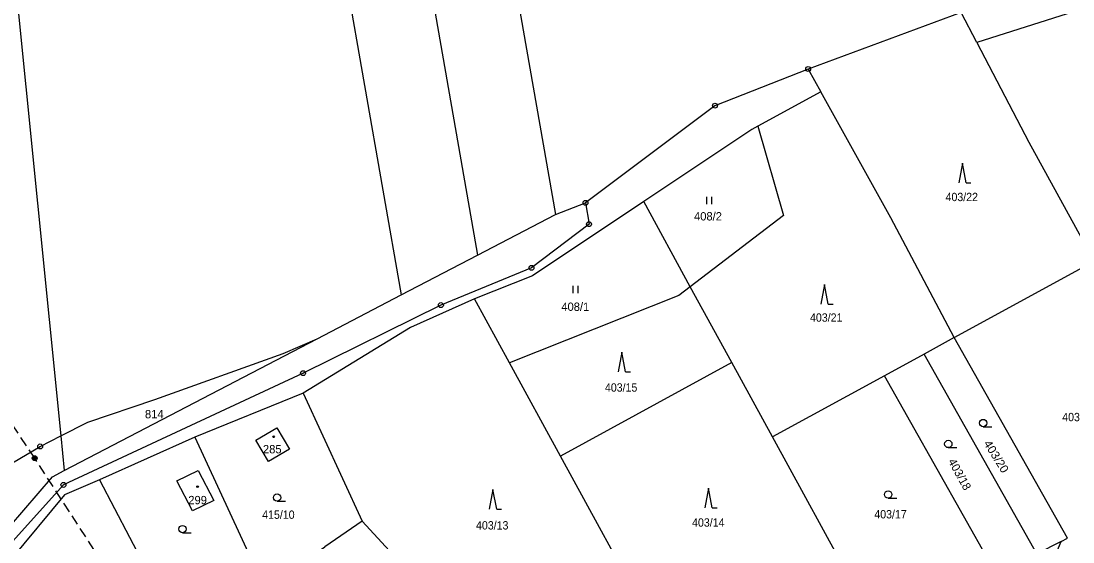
# Model space of a CAD drawing. Extents: x -754445 to -751443, y -1030748 to -1028224.
# Drawn here: x -753502.6 to -753288.1, y -1028882.4 to -1028776.1 of the extents above; entities that cross this region are included whole.
import ezdxf
from ezdxf.enums import TextEntityAlignment as Align

# ---------------------------------------------------------------- set-up
doc = ezdxf.new("R2010")
doc.units = 0
doc.header["$LTSCALE"] = 0.68
doc.linetypes.add('MEDIUM_DASHED', pattern=[4.5, 3, -1.5])
for name, color, linetype, lineweight in [('1', 7, 'Continuous', 25), ('3', 7, 'Continuous', 25), ('5', 7, 'Continuous', 25), ('6', 7, 'Continuous', 25), ('8', 7, 'Continuous', 25)]:
    doc.layers.add(name, color=color, linetype=linetype, lineweight=lineweight)
doc.layers.add('2', color=7, linetype='Continuous')

msp = doc.modelspace()

# ---------------------------------------------------------------- linework, layer by layer
at = {"layer": '1'}
for p, q in [((-753366.13, -1028830.34), (-753375.62, -1028812.97)), ((-753312.31, -1028840.7), (-753283.77, -1028825.1)), ((-753442.2, -1028840.92), (-753425.07, -1028831.99)), ((-753403, -1028845.85), (-753410.13, -1028832.81)), ((-753312.31, -1028840.7), (-753318.45, -1028844.06)), ((-753357.68, -1028845.79), (-753392.6, -1028864.88)), ((-753326.53, -1028848.47), (-753349.38, -1028860.96)), ((-753305.08, -1028886.55), (-753326.53, -1028848.47)), ((-753445.06, -1028852.06), (-753433.06, -1028878.13)), ((-753467.15, -1028860.99), (-753486.58, -1028869.72)), ((-753486.58, -1028869.72), (-753469.8, -1028901.88))]:
    msp.add_line(p, q, dxfattribs=at)
for points in [[(-753436.39, -1028571.31), (-753415.01, -1028693.46), (-753393.62, -1028815.6), (-753387.5, -1028813.22)], [(-753453.37, -1028573.55), (-753431.45, -1028698.72), (-753409.53, -1028823.89), (-753393.62, -1028815.6)], [(-753469.94, -1028575.74), (-753522.37, -1028582.66), (-753504.02, -1028765.76), (-753494.5, -1028860.74)], [(-753469.94, -1028575.74), (-753447.51, -1028703.87), (-753425.07, -1028831.99), (-753409.53, -1028823.89)], [(-753212.4, -1028772.78), (-753253.9, -1028764.59), (-753277.92, -1028771.03), (-753307.71, -1028780.5)], [(-753307.71, -1028780.5), (-753310.91, -1028774.39), (-753342.1, -1028785.93), (-753339.5, -1028790.61)], [(-753307.71, -1028780.5), (-753297.08, -1028800.82), (-753283.77, -1028825.1)], [(-753342.1, -1028785.93), (-753361.1, -1028793.41), (-753387.5, -1028813.22)], [(-753312.31, -1028840.7), (-753325.25, -1028816.3), (-753339.5, -1028790.61), (-753352.36, -1028797.59)], [(-753352.36, -1028797.59), (-753353.62, -1028798.28), (-753375.62, -1028812.97)], [(-753352.36, -1028797.59), (-753347.14, -1028815.78), (-753366.13, -1028830.34)], [(-753375.62, -1028812.97), (-753398.32, -1028828.13), (-753410.13, -1028832.81)], [(-753387.5, -1028813.22), (-753386.79, -1028817.57), (-753398.52, -1028826.47), (-753416.99, -1028834.07), (-753445.1, -1028847.96), (-753493.97, -1028870.74), (-753530.03, -1028910.75), (-753559.13, -1028932.46), (-753562.04, -1028932.8), (-753565.98, -1028933.27)], [(-753366.13, -1028830.34), (-753368.5, -1028832.14), (-753403, -1028845.85)], [(-753332.6, -1028891.68), (-753349.38, -1028860.96), (-753357.68, -1028845.79), (-753366.13, -1028830.34)], [(-753410.13, -1028832.81), (-753423.16, -1028838.67), (-753445.06, -1028852.06)], [(-753494.5, -1028860.74), (-753488.97, -1028857.93), (-753475.3, -1028853.33), (-753449.14, -1028843.94), (-753442.2, -1028840.92)], [(-753494.5, -1028860.74), (-753493.79, -1028867.8), (-753442.2, -1028840.92)], [(-753290.53, -1028882.28), (-753289.21, -1028881.62), (-753312.31, -1028840.7)], [(-753297.57, -1028885.92), (-753295.46, -1028884.79), (-753318.45, -1028844.06), (-753326.53, -1028848.47)], [(-753374.33, -1028898.31), (-753392.6, -1028864.88), (-753403, -1028845.85)], [(-753445.06, -1028852.06), (-753467.15, -1028860.99), (-753452.93, -1028891.89), (-753440.64, -1028883.38)], [(-753564.85, -1028896.16), (-753552.13, -1028891.01), (-753542.49, -1028886.82), (-753526.62, -1028879.38), (-753498.71, -1028862.89), (-753494.5, -1028860.74)], [(-753564.85, -1028896.16), (-753562.94, -1028899.35), (-753556.56, -1028902.74), (-753552.81, -1028903.73), (-753545.48, -1028902.83), (-753537.53, -1028901), (-753530, -1028895.31), (-753524.69, -1028887.31), (-753521.7, -1028886.05), (-753518.8, -1028891.25), (-753537.63, -1028904.39), (-753548.66, -1028906.43), (-753554.79, -1028906.57), (-753556.39, -1028910.21), (-753557.13, -1028917.11), (-753556.35, -1028919.43), (-753554.65, -1028920.99), (-753552.51, -1028921.64), (-753550.17, -1028921.47), (-753548.23, -1028921.2), (-753534.97, -1028911.67), (-753522.59, -1028899.68), (-753496.2, -1028869.06), (-753493.79, -1028867.8)], [(-753486.58, -1028869.72), (-753493.77, -1028872.77), (-753504.67, -1028885.95)], [(-753398.05, -1028919.59), (-753402.77, -1028910.96), (-753433.06, -1028878.13), (-753440.64, -1028883.38)], [(-753294.67, -1028892.21), (-753290.53, -1028882.28), (-753295.46, -1028884.79)]]:
    msp.add_lwpolyline(points, dxfattribs=at)
for points in [[(-753450.42, -1028859.09), (-753447.85, -1028863.42), (-753452.13, -1028865.96), (-753454.71, -1028861.63)], [(-753466.48, -1028867.81), (-753463.3, -1028873.89), (-753467.63, -1028876.03), (-753470.81, -1028869.93)]]:
    msp.add_lwpolyline(points, close=True, dxfattribs=at)
at = {"layer": '3'}
for p, q in [((-753309.91, -1028809.11), (-753308.914, -1028809.11)), ((-753362.771, -1028813.48), (-753362.771, -1028811.98)), ((-753361.77, -1028813.48), (-753361.77, -1028811.98)), ((-753390.001, -1028831.65), (-753390.001, -1028830.15)), ((-753389, -1028831.65), (-753389, -1028830.15)), ((-753337.99, -1028833.89), (-753336.994, -1028833.89)), ((-753379.33, -1028847.69), (-753378.334, -1028847.69)), ((-753306.413, -1028858.87), (-753304.663, -1028858.87)), ((-753313.523, -1028863.14), (-753311.773, -1028863.14)), ((-753450.403, -1028874.07), (-753448.653, -1028874.07)), ((-753325.793, -1028873.45), (-753324.043, -1028873.45)), ((-753405.62, -1028875.69), (-753404.624, -1028875.69)), ((-753361.67, -1028875.41), (-753360.674, -1028875.41)), ((-753469.673, -1028880.49), (-753467.923, -1028880.49))]:
    msp.add_line(p, q, dxfattribs=at)
for points in [[(-753309.91, -1028809.11), (-753310.66, -1028805.11), (-753311.41, -1028809.11)], [(-753337.99, -1028833.89), (-753338.74, -1028829.89), (-753339.49, -1028833.89)], [(-753379.33, -1028847.69), (-753380.08, -1028843.69), (-753380.83, -1028847.69)], [(-753405.62, -1028875.69), (-753406.37, -1028871.69), (-753407.12, -1028875.69)], [(-753361.67, -1028875.41), (-753362.42, -1028871.41), (-753363.17, -1028875.41)]]:
    msp.add_lwpolyline(points, dxfattribs=at)
for centre in [(-753306.4129, -1028858.1198), (-753313.5229, -1028862.3898), (-753450.4029, -1028873.3198), (-753325.7929, -1028872.6998), (-753469.6729, -1028879.7398)]:
    msp.add_circle(centre, 0.75, dxfattribs=at)
at = {"layer": '5'}
for centre in [(-753451.0868, -1028860.9192), (-753466.6168, -1028871.0992)]:
    msp.add_circle(centre, 0.175, dxfattribs=at)
at = {"layer": '6', "linetype": 'MEDIUM_DASHED'}
msp.add_line((-753474.45, -1028904.45), (-753499.83, -1028865.29), dxfattribs=at)
msp.add_lwpolyline([(-753499.83, -1028865.29), (-753527.61, -1028823.3), (-753570.95, -1028756.74), (-753608.62, -1028714.93), (-753648.01, -1028671.11), (-753702.8, -1028610.73), (-753758.07, -1028549.45), (-753816.14, -1028485.34), (-753875.16, -1028419.8), (-753934.32, -1028354.21)], dxfattribs=at)
at = {"layer": '6'}
for radius in [0.5, 0.4, 0.3, 0.2, 0.1]:
    msp.add_circle((-753499.8334, -1028865.2899), radius, dxfattribs=at)
at = {"layer": '8'}
for centre, radius in [((-753342.1, -1028785.9299), 0.5), ((-753342.1, -1028785.9299), 0.0303), ((-753361.1, -1028793.4099), 0.5), ((-753361.1, -1028793.4099), 0.0303), ((-753387.5, -1028813.2199), 0.5), ((-753387.5, -1028813.2199), 0.0303), ((-753386.79, -1028817.5699), 0.5), ((-753386.79, -1028817.5699), 0.0303), ((-753398.52, -1028826.4699), 0.5), ((-753398.52, -1028826.4699), 0.0303), ((-753416.99, -1028834.0699), 0.5), ((-753416.99, -1028834.0699), 0.0303), ((-753445.1, -1028847.9599), 0.5), ((-753445.1, -1028847.9599), 0.0303), ((-753498.71, -1028862.8899), 0.5), ((-753498.71, -1028862.8899), 0.0303), ((-753493.97, -1028870.7399), 0.5), ((-753493.97, -1028870.7399), 0.0303)]:
    msp.add_circle(centre, radius, dxfattribs=at)

# ---------------------------------------------------------------- texts
at = {"layer": '2', "width": 0.95}
for s, p in [('403/22', (-753310.779, -1028812.87)), ('403/21', (-753338.419, -1028837.46)), ('403/15', (-753380.239, -1028851.72)), ('403/23', (-753286.989, -1028857.75)), ('415/10', (-753450.129, -1028877.65)), ('403/14', (-753362.469, -1028879.25)), ('403/17', (-753325.309, -1028877.57)), ('403/13', (-753406.529, -1028879.83))]:
    msp.add_text(s, height=1.7, dxfattribs=at).set_placement(p, align=Align.CENTER)
at = {"layer": '2'}
for s, p in [('408/2', (-753362.53, -1028816.81)), ('408/1', (-753389.59, -1028835.25)), ('814', (-753475.439, -1028857.156)), ('285', (-753451.379, -1028864.3))]:
    msp.add_text(s, height=1.7, dxfattribs=at).set_placement(p, align=Align.CENTER)
at = {"layer": '2', "width": 1.05}
msp.add_text('403/20', height=1.7, rotation=302, dxfattribs=at).set_placement((-753304.4527, -1028865.3906), align=Align.CENTER)
at = {"layer": '2'}
msp.add_text('403/18', height=1.7, rotation=299, dxfattribs=at).set_placement((-753311.9411, -1028868.9859), align=Align.CENTER)
msp.add_text('299', height=1.7, dxfattribs=at).set_placement((-753468.5, -1028874.68))

doc.saveas('drawing.dxf')
